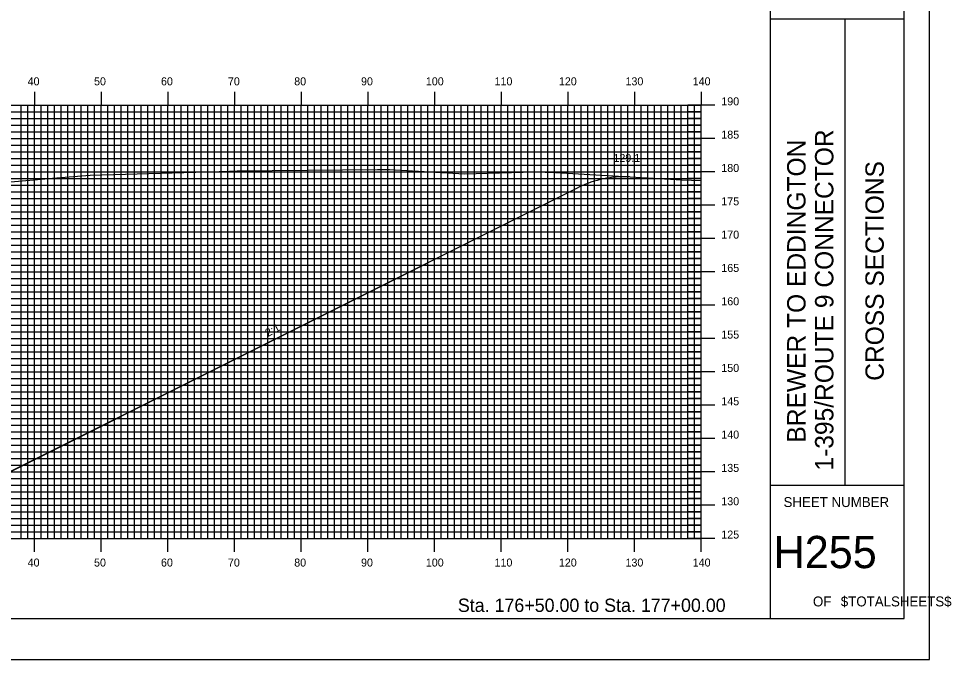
# Model space of a CAD drawing. Extents: x 1784615 to 1784958, y 442591 to 442811.
# Drawn here: x 1784818.1 to 1784958, y 442590.5 to 442686.7 of the extents above; entities that cross this region are included whole.
import ezdxf

# ---------------------------------------------------------------- set-up
doc = ezdxf.new("R2010")
doc.units = 0
for name, color, linetype in [('ANNOTATION', 7, 'Continuous'), ('BORDER', 7, 'Continuous'), ('D_Roadway_Centerline', 7, 'Continuous'), ('D_Roadway_SlopeLines', 7, 'Continuous'), ('D_Text_Standard', 7, 'Continuous'), ('H_V ANNOTATION', 7, 'Continuous'), ('MAJOR', 7, 'Continuous'), ('MINOR', 7, 'Continuous'), ('PLOT BOUNDARY', 7, 'Continuous'), ('S_Roadway_Centerline', 7, 'Continuous')]:
    doc.layers.add(name, color=color, linetype=linetype)

msp = doc.modelspace()

# ---------------------------------------------------------------- linework, layer by layer
at = {"layer": 'BORDER'}
for p, q in [((1784930.91, 442596.67), (1784930.91, 442806.67)), ((1784930.91, 442686.67), (1784950.91, 442686.67)), ((1784930.91, 442686.67), (1784950.91, 442686.67)), ((1784942.09, 442616.67), (1784942.09, 442686.67)), ((1784942.09, 442616.67), (1784942.09, 442686.67)), ((1784930.91, 442616.67), (1784950.91, 442616.67)), ((1784930.91, 442616.67), (1784950.91, 442616.67))]:
    msp.add_line(p, q, dxfattribs=at)
msp.add_lwpolyline([(1784630.91, 442596.67), (1784950.91, 442596.67), (1784950.91, 442806.67), (1784630.91, 442806.67)], close=True, dxfattribs=at)
at = {"layer": 'D_Roadway_Centerline'}
msp.add_lwpolyline([(1784685.99, 442642.94), (1784687.24, 442642.9), (1784688.49, 442642.7), (1784689.74, 442642.32), (1784690.99, 442641.78), (1784746.34, 442614.11), (1784750.34, 442615.11), (1784760.51, 442617.65), (1784768.51, 442617.97), (1784780.51, 442618.24), (1784792.51, 442618.5), (1784800.51, 442618.18), (1784810.69, 442615.64), (1784902.15, 442661.37)], dxfattribs=at)
at = {"layer": 'D_Roadway_SlopeLines'}
msp.add_line((1784812.69, 442616.64), (1784902.15, 442661.37), dxfattribs=at)
msp.add_arc((1784908.86, 442647.95), 15, 86.7069, 116.5651, dxfattribs=at)
at = {"layer": 'MAJOR'}
for p, q in [((1784820.51, 442675.67), (1784820.51, 442673.67)), ((1784830.51, 442675.67), (1784830.51, 442673.67)), ((1784840.51, 442675.67), (1784840.51, 442673.67)), ((1784850.51, 442675.67), (1784850.51, 442673.67)), ((1784860.51, 442675.67), (1784860.51, 442673.67)), ((1784870.51, 442675.67), (1784870.51, 442673.67)), ((1784880.51, 442675.67), (1784880.51, 442673.67)), ((1784890.51, 442675.67), (1784890.51, 442673.67)), ((1784900.51, 442675.67), (1784900.51, 442673.67)), ((1784910.51, 442675.67), (1784910.51, 442673.67)), ((1784920.51, 442675.67), (1784920.51, 442673.67)), ((1784640.51, 442673.67), (1784920.51, 442673.67)), ((1784640.51, 442673.67), (1784920.51, 442673.67)), ((1784820.51, 442608.67), (1784820.51, 442673.67)), ((1784830.51, 442608.67), (1784830.51, 442673.67)), ((1784840.51, 442608.67), (1784840.51, 442673.67)), ((1784850.51, 442608.67), (1784850.51, 442673.67)), ((1784860.51, 442608.67), (1784860.51, 442673.67)), ((1784870.51, 442608.67), (1784870.51, 442673.67)), ((1784880.51, 442608.67), (1784880.51, 442673.67)), ((1784890.51, 442608.67), (1784890.51, 442673.67)), ((1784900.51, 442608.67), (1784900.51, 442673.67)), ((1784910.51, 442608.67), (1784910.51, 442673.67)), ((1784922.52, 442673.67), (1784918.51, 442673.67)), ((1784920.51, 442608.67), (1784920.51, 442673.67)), ((1784920.51, 442608.67), (1784920.51, 442673.67)), ((1784640.51, 442668.67), (1784920.51, 442668.67)), ((1784922.52, 442668.67), (1784918.51, 442668.67)), ((1784640.51, 442663.67), (1784920.51, 442663.67)), ((1784922.52, 442663.67), (1784918.51, 442663.67)), ((1784640.51, 442658.67), (1784920.51, 442658.67)), ((1784922.52, 442658.67), (1784918.51, 442658.67)), ((1784640.51, 442653.67), (1784920.51, 442653.67)), ((1784922.52, 442653.67), (1784918.51, 442653.67)), ((1784640.51, 442648.67), (1784920.51, 442648.67)), ((1784922.52, 442648.67), (1784918.51, 442648.67)), ((1784640.51, 442643.67), (1784920.51, 442643.67)), ((1784922.52, 442643.67), (1784918.51, 442643.67)), ((1784640.51, 442638.67), (1784920.51, 442638.67)), ((1784922.52, 442638.67), (1784918.51, 442638.67)), ((1784640.51, 442633.67), (1784920.51, 442633.67)), ((1784922.52, 442633.67), (1784918.51, 442633.67)), ((1784640.51, 442628.67), (1784920.51, 442628.67)), ((1784922.52, 442628.67), (1784918.51, 442628.67)), ((1784640.51, 442623.67), (1784920.51, 442623.67)), ((1784922.52, 442623.67), (1784918.51, 442623.67)), ((1784640.51, 442618.67), (1784920.51, 442618.67)), ((1784922.52, 442618.67), (1784918.51, 442618.67)), ((1784640.51, 442613.67), (1784920.51, 442613.67)), ((1784922.52, 442613.67), (1784918.51, 442613.67)), ((1784640.51, 442608.67), (1784920.51, 442608.67)), ((1784820.51, 442606.66), (1784820.51, 442608.67)), ((1784830.51, 442606.66), (1784830.51, 442608.67)), ((1784840.51, 442606.66), (1784840.51, 442608.67)), ((1784850.51, 442606.66), (1784850.51, 442608.67)), ((1784860.51, 442606.66), (1784860.51, 442608.67)), ((1784870.51, 442606.66), (1784870.51, 442608.67)), ((1784880.51, 442606.66), (1784880.51, 442608.67)), ((1784890.51, 442606.66), (1784890.51, 442608.67)), ((1784900.51, 442606.66), (1784900.51, 442608.67)), ((1784910.51, 442606.66), (1784910.51, 442608.67)), ((1784922.52, 442608.67), (1784918.51, 442608.67)), ((1784920.51, 442606.66), (1784920.51, 442608.67))]:
    msp.add_line(p, q, dxfattribs=at)
at = {"layer": 'MINOR'}
for p, q in [((1784818.51, 442608.67), (1784818.51, 442673.67)), ((1784819.51, 442608.67), (1784819.51, 442673.67)), ((1784821.51, 442608.67), (1784821.51, 442673.67)), ((1784822.51, 442608.67), (1784822.51, 442673.67)), ((1784823.51, 442608.67), (1784823.51, 442673.67)), ((1784824.51, 442608.67), (1784824.51, 442673.67)), ((1784825.51, 442608.67), (1784825.51, 442673.67)), ((1784826.51, 442608.67), (1784826.51, 442673.67)), ((1784827.51, 442608.67), (1784827.51, 442673.67)), ((1784828.51, 442608.67), (1784828.51, 442673.67)), ((1784829.51, 442608.67), (1784829.51, 442673.67)), ((1784831.51, 442608.67), (1784831.51, 442673.67)), ((1784832.51, 442608.67), (1784832.51, 442673.67)), ((1784833.51, 442608.67), (1784833.51, 442673.67)), ((1784834.51, 442608.67), (1784834.51, 442673.67)), ((1784835.51, 442608.67), (1784835.51, 442673.67)), ((1784836.51, 442608.67), (1784836.51, 442673.67)), ((1784837.51, 442608.67), (1784837.51, 442673.67)), ((1784838.51, 442608.67), (1784838.51, 442673.67)), ((1784839.51, 442608.67), (1784839.51, 442673.67)), ((1784841.51, 442608.67), (1784841.51, 442673.67)), ((1784842.51, 442608.67), (1784842.51, 442673.67)), ((1784843.51, 442608.67), (1784843.51, 442673.67)), ((1784844.51, 442608.67), (1784844.51, 442673.67)), ((1784845.51, 442608.67), (1784845.51, 442673.67)), ((1784846.51, 442608.67), (1784846.51, 442673.67)), ((1784847.51, 442608.67), (1784847.51, 442673.67)), ((1784848.51, 442608.67), (1784848.51, 442673.67)), ((1784849.51, 442608.67), (1784849.51, 442673.67)), ((1784851.51, 442608.67), (1784851.51, 442673.67)), ((1784852.51, 442608.67), (1784852.51, 442673.67)), ((1784853.51, 442608.67), (1784853.51, 442673.67)), ((1784854.51, 442608.67), (1784854.51, 442673.67)), ((1784855.51, 442608.67), (1784855.51, 442673.67)), ((1784856.51, 442608.67), (1784856.51, 442673.67)), ((1784857.51, 442608.67), (1784857.51, 442673.67)), ((1784858.51, 442608.67), (1784858.51, 442673.67)), ((1784859.51, 442608.67), (1784859.51, 442673.67)), ((1784861.51, 442608.67), (1784861.51, 442673.67)), ((1784862.51, 442608.67), (1784862.51, 442673.67)), ((1784863.51, 442608.67), (1784863.51, 442673.67)), ((1784864.51, 442608.67), (1784864.51, 442673.67)), ((1784865.51, 442608.67), (1784865.51, 442673.67)), ((1784866.51, 442608.67), (1784866.51, 442673.67)), ((1784867.51, 442608.67), (1784867.51, 442673.67)), ((1784868.51, 442608.67), (1784868.51, 442673.67)), ((1784869.51, 442608.67), (1784869.51, 442673.67)), ((1784871.51, 442608.67), (1784871.51, 442673.67)), ((1784872.51, 442608.67), (1784872.51, 442673.67)), ((1784873.51, 442608.67), (1784873.51, 442673.67)), ((1784874.51, 442608.67), (1784874.51, 442673.67)), ((1784875.51, 442608.67), (1784875.51, 442673.67)), ((1784876.51, 442608.67), (1784876.51, 442673.67)), ((1784877.51, 442608.67), (1784877.51, 442673.67)), ((1784878.51, 442608.67), (1784878.51, 442673.67)), ((1784879.51, 442608.67), (1784879.51, 442673.67)), ((1784881.51, 442608.67), (1784881.51, 442673.67)), ((1784882.51, 442608.67), (1784882.51, 442673.67)), ((1784883.51, 442608.67), (1784883.51, 442673.67)), ((1784884.51, 442608.67), (1784884.51, 442673.67)), ((1784885.51, 442608.67), (1784885.51, 442673.67)), ((1784886.51, 442608.67), (1784886.51, 442673.67)), ((1784887.51, 442608.67), (1784887.51, 442673.67)), ((1784888.51, 442608.67), (1784888.51, 442673.67)), ((1784889.51, 442608.67), (1784889.51, 442673.67)), ((1784891.51, 442608.67), (1784891.51, 442673.67)), ((1784892.51, 442608.67), (1784892.51, 442673.67)), ((1784893.51, 442608.67), (1784893.51, 442673.67)), ((1784894.51, 442608.67), (1784894.51, 442673.67)), ((1784895.51, 442608.67), (1784895.51, 442673.67)), ((1784896.51, 442608.67), (1784896.51, 442673.67)), ((1784897.51, 442608.67), (1784897.51, 442673.67)), ((1784898.51, 442608.67), (1784898.51, 442673.67)), ((1784899.51, 442608.67), (1784899.51, 442673.67)), ((1784901.51, 442608.67), (1784901.51, 442673.67)), ((1784902.51, 442608.67), (1784902.51, 442673.67)), ((1784903.51, 442608.67), (1784903.51, 442673.67)), ((1784904.51, 442608.67), (1784904.51, 442673.67)), ((1784905.51, 442608.67), (1784905.51, 442673.67)), ((1784906.51, 442608.67), (1784906.51, 442673.67)), ((1784907.51, 442608.67), (1784907.51, 442673.67)), ((1784908.51, 442608.67), (1784908.51, 442673.67)), ((1784909.51, 442608.67), (1784909.51, 442673.67)), ((1784911.51, 442608.67), (1784911.51, 442673.67)), ((1784912.51, 442608.67), (1784912.51, 442673.67)), ((1784913.51, 442608.67), (1784913.51, 442673.67)), ((1784914.51, 442608.67), (1784914.51, 442673.67)), ((1784915.51, 442608.67), (1784915.51, 442673.67)), ((1784916.51, 442608.67), (1784916.51, 442673.67)), ((1784917.51, 442608.67), (1784917.51, 442673.67)), ((1784918.51, 442608.67), (1784918.51, 442673.67)), ((1784919.51, 442608.67), (1784919.51, 442673.67)), ((1784640.51, 442672.67), (1784920.51, 442672.67)), ((1784640.51, 442671.67), (1784920.51, 442671.67)), ((1784920.51, 442672.67), (1784918.51, 442672.67)), ((1784920.51, 442671.67), (1784918.51, 442671.67)), ((1784640.51, 442670.67), (1784920.51, 442670.67)), ((1784920.51, 442670.67), (1784918.51, 442670.67)), ((1784640.51, 442669.67), (1784920.51, 442669.67)), ((1784920.51, 442669.67), (1784918.51, 442669.67)), ((1784640.51, 442667.67), (1784920.51, 442667.67)), ((1784920.51, 442667.67), (1784918.51, 442667.67)), ((1784640.51, 442666.67), (1784920.51, 442666.67)), ((1784920.51, 442666.67), (1784918.51, 442666.67)), ((1784640.51, 442665.67), (1784920.51, 442665.67)), ((1784640.51, 442664.67), (1784920.51, 442664.67)), ((1784920.51, 442665.67), (1784918.51, 442665.67)), ((1784920.51, 442664.67), (1784918.51, 442664.67)), ((1784640.51, 442662.67), (1784920.51, 442662.67)), ((1784920.51, 442662.67), (1784918.51, 442662.67)), ((1784640.51, 442661.67), (1784920.51, 442661.67)), ((1784640.51, 442660.67), (1784920.51, 442660.67)), ((1784920.51, 442661.67), (1784918.51, 442661.67)), ((1784920.51, 442660.67), (1784918.51, 442660.67)), ((1784640.51, 442659.67), (1784920.51, 442659.67)), ((1784920.51, 442659.67), (1784918.51, 442659.67)), ((1784640.51, 442657.67), (1784920.51, 442657.67)), ((1784920.51, 442657.67), (1784918.51, 442657.67)), ((1784640.51, 442656.67), (1784920.51, 442656.67)), ((1784920.51, 442656.67), (1784918.51, 442656.67)), ((1784640.51, 442655.67), (1784920.51, 442655.67)), ((1784920.51, 442655.67), (1784918.51, 442655.67)), ((1784640.51, 442654.67), (1784920.51, 442654.67)), ((1784920.51, 442654.67), (1784918.51, 442654.67)), ((1784640.51, 442652.67), (1784920.51, 442652.67)), ((1784920.51, 442652.67), (1784918.51, 442652.67)), ((1784640.51, 442651.67), (1784920.51, 442651.67)), ((1784640.51, 442650.67), (1784920.51, 442650.67)), ((1784920.51, 442651.67), (1784918.51, 442651.67)), ((1784920.51, 442650.67), (1784918.51, 442650.67)), ((1784640.51, 442649.67), (1784920.51, 442649.67)), ((1784920.51, 442649.67), (1784918.51, 442649.67)), ((1784640.51, 442647.67), (1784920.51, 442647.67)), ((1784640.51, 442646.67), (1784920.51, 442646.67)), ((1784920.51, 442647.67), (1784918.51, 442647.67)), ((1784920.51, 442646.67), (1784918.51, 442646.67)), ((1784640.51, 442645.67), (1784920.51, 442645.67)), ((1784920.51, 442645.67), (1784918.51, 442645.67)), ((1784640.51, 442644.67), (1784920.51, 442644.67)), ((1784920.51, 442644.67), (1784918.51, 442644.67)), ((1784640.51, 442642.67), (1784920.51, 442642.67)), ((1784920.51, 442642.67), (1784918.51, 442642.67)), ((1784640.51, 442641.67), (1784920.51, 442641.67)), ((1784920.51, 442641.67), (1784918.51, 442641.67)), ((1784640.51, 442640.67), (1784920.51, 442640.67)), ((1784640.51, 442639.67), (1784920.51, 442639.67)), ((1784920.51, 442640.67), (1784918.51, 442640.67)), ((1784920.51, 442639.67), (1784918.51, 442639.67)), ((1784640.51, 442637.67), (1784920.51, 442637.67)), ((1784640.51, 442636.67), (1784920.51, 442636.67)), ((1784920.51, 442637.67), (1784918.51, 442637.67)), ((1784920.51, 442636.67), (1784918.51, 442636.67)), ((1784640.51, 442635.67), (1784920.51, 442635.67)), ((1784920.51, 442635.67), (1784918.51, 442635.67)), ((1784640.51, 442634.67), (1784920.51, 442634.67)), ((1784920.51, 442634.67), (1784918.51, 442634.67)), ((1784640.51, 442632.67), (1784920.51, 442632.67)), ((1784920.51, 442632.67), (1784918.51, 442632.67)), ((1784640.51, 442631.67), (1784920.51, 442631.67)), ((1784920.51, 442631.67), (1784918.51, 442631.67)), ((1784640.51, 442630.67), (1784920.51, 442630.67)), ((1784640.51, 442629.67), (1784920.51, 442629.67)), ((1784920.51, 442630.67), (1784918.51, 442630.67)), ((1784920.51, 442629.67), (1784918.51, 442629.67)), ((1784640.51, 442627.67), (1784920.51, 442627.67)), ((1784920.51, 442627.67), (1784918.51, 442627.67)), ((1784640.51, 442626.67), (1784920.51, 442626.67)), ((1784640.51, 442625.67), (1784920.51, 442625.67)), ((1784920.51, 442626.67), (1784918.51, 442626.67)), ((1784920.51, 442625.67), (1784918.51, 442625.67)), ((1784640.51, 442624.67), (1784920.51, 442624.67)), ((1784920.51, 442624.67), (1784918.51, 442624.67)), ((1784640.51, 442622.67), (1784920.51, 442622.67)), ((1784920.51, 442622.67), (1784918.51, 442622.67)), ((1784640.51, 442621.67), (1784920.51, 442621.67)), ((1784920.51, 442621.67), (1784918.51, 442621.67)), ((1784640.51, 442620.67), (1784920.51, 442620.67)), ((1784920.51, 442620.67), (1784918.51, 442620.67)), ((1784640.51, 442619.67), (1784920.51, 442619.67)), ((1784920.51, 442619.67), (1784918.51, 442619.67)), ((1784640.51, 442617.67), (1784920.51, 442617.67)), ((1784920.51, 442617.67), (1784918.51, 442617.67)), ((1784640.51, 442616.67), (1784920.51, 442616.67)), ((1784640.51, 442615.67), (1784920.51, 442615.67)), ((1784920.51, 442616.67), (1784918.51, 442616.67)), ((1784920.51, 442615.67), (1784918.51, 442615.67)), ((1784640.51, 442614.67), (1784920.51, 442614.67)), ((1784920.51, 442614.67), (1784918.51, 442614.67)), ((1784640.51, 442612.67), (1784920.51, 442612.67)), ((1784640.51, 442611.67), (1784920.51, 442611.67)), ((1784920.51, 442612.67), (1784918.51, 442612.67)), ((1784920.51, 442611.67), (1784918.51, 442611.67)), ((1784640.51, 442610.67), (1784920.51, 442610.67)), ((1784920.51, 442610.67), (1784918.51, 442610.67)), ((1784640.51, 442609.67), (1784920.51, 442609.67)), ((1784920.51, 442609.67), (1784918.51, 442609.67))]:
    msp.add_line(p, q, dxfattribs=at)
at = {"layer": 'PLOT BOUNDARY'}
msp.add_lwpolyline([(1784614.73, 442590.55), (1784954.73, 442590.55), (1784954.73, 442810.55), (1784614.73, 442810.55)], close=True, dxfattribs=at)
at = {"layer": 'S_Roadway_Centerline'}
msp.add_lwpolyline([(1784807.8, 442661.4), (1784823.23, 442662.76), (1784828.88, 442663.17), (1784848.21, 442663.75), (1784849.76, 442663.8), (1784850.89, 442663.85), (1784871.95, 442664.04), (1784873.73, 442664.04), (1784884.99, 442663.41), (1784895.52, 442663.67), (1784898.64, 442663.57), (1784917.6, 442662.47), (1784920.51, 442662.4)], dxfattribs=at)

# ---------------------------------------------------------------- texts
at = {"layer": 'ANNOTATION'}
msp.add_text('2:1', height=1.2, rotation=28.7672, dxfattribs=at).set_placement((1784855.52, 442638.9))
at = {"layer": 'BORDER'}
for s, p in [('1-395/ROUTE 9 CONNECTOR', (1784940.32, 442618.87)), ('BREWER TO EDDINGTON', (1784936.14, 442623.07)), ('CROSS SECTIONS', (1784947.88, 442632.34)), ('CROSS SECTIONS', (1784947.88, 442632.34))]:
    msp.add_text(s, height=2.7557, rotation=90, dxfattribs=at).set_placement(p)
for s, height, p in [('SHEET NUMBER', 1.4905, (1784932.84, 442613.4)), ('SHEET NUMBER', 1.4905, (1784932.84, 442613.4)), ('H255', 4.839, (1784931.35, 442604.23)), ('OF', 1.491, (1784937.25, 442598.49)), ('OF', 1.491, (1784937.25, 442598.49)), ('$TOTALSHEETS$', 1.4905, (1784941.43, 442598.49))]:
    msp.add_text(s, height=height, dxfattribs=at).set_placement(p)
at = {"layer": 'D_Text_Standard'}
msp.add_text("129.1'", height=1.2, dxfattribs=at).set_placement((1784907.33, 442665.17))
at = {"layer": 'H_V ANNOTATION'}
for s, height, p in [('40', 1.2, (1784819.48, 442676.67)), ('50', 1.2, (1784829.44, 442676.67)), ('60', 1.2, (1784839.48, 442676.67)), ('70', 1.2, (1784849.52, 442676.67)), ('80', 1.2, (1784859.46, 442676.67)), ('90', 1.2, (1784869.48, 442676.67)), ('100', 1.2, (1784879.2, 442676.67)), ('110', 1.2, (1784889.5, 442676.67)), ('120', 1.2, (1784899.15, 442676.67)), ('130', 1.2, (1784909.14, 442676.67)), ('140', 1.2, (1784919.22, 442676.67)), ('190', 1.2, (1784923.51, 442673.67)), ('185', 1.2, (1784923.51, 442668.67)), ('180', 1.2, (1784923.51, 442663.67)), ('175', 1.2, (1784923.51, 442658.67)), ('170', 1.2, (1784923.51, 442653.67)), ('165', 1.2, (1784923.51, 442648.67)), ('160', 1.2, (1784923.51, 442643.67)), ('155', 1.2, (1784923.51, 442638.67)), ('150', 1.2, (1784923.51, 442633.67)), ('145', 1.2, (1784923.51, 442628.67)), ('140', 1.2, (1784923.51, 442623.67)), ('135', 1.2, (1784923.51, 442618.67)), ('130', 1.2, (1784923.51, 442613.67)), ('125', 1.2, (1784923.51, 442608.67)), ('40', 1.2, (1784819.48, 442604.47)), ('50', 1.2, (1784829.44, 442604.47)), ('60', 1.2, (1784839.48, 442604.47)), ('70', 1.2, (1784849.52, 442604.47)), ('80', 1.2, (1784859.46, 442604.47)), ('90', 1.2, (1784869.48, 442604.47)), ('100', 1.2, (1784879.2, 442604.47)), ('110', 1.2, (1784889.5, 442604.47)), ('120', 1.2, (1784899.15, 442604.47)), ('130', 1.2, (1784909.14, 442604.47)), ('140', 1.2, (1784919.22, 442604.47)), ('Sta. 176+50.00 to Sta. 177+00.00', 2.0004, (1784884, 442597.66))]:
    msp.add_text(s, height=height, dxfattribs=at).set_placement(p)

doc.saveas('drawing.dxf')
